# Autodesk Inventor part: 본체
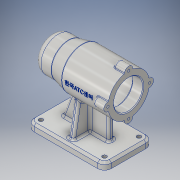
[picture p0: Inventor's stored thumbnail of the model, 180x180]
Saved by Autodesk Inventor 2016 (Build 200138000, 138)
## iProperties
Created: 2019-07
Part Number: 본체
Material: 알루미늄 6061
Document SubType Name: Modeling
Designer: 3sil_0101
Density: 2.7 g/cm^3
Appearance: 알루미늄 - 평지
Mass: 644.388 g
Surface Area: 654.094 cm^2
Volume: 238.662 cm^3
Author: 3sil_0101
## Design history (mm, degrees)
sketch "스케치1"
  geometry: L1 (56, 35)-(-56, 35); L2 (-56, 35)-(-56, -35); L3 (-56, -35)-(56, -35); L4 (56, -35)-(56, 35); L5 (56, 35)-(-56, -35); L6 (-56, 35)-(56, -35); 1 further point
  constraints: 12 end point, 2 midpoint, 2 parallel, 1 horizontal, 1 perpendicular
  dimensions: "d0" = 70 distance between parallel lines of L1 L3; "d1" = 112 distance between parallel lines of L4 L2
extrude "돌출1" new body sketch "스케치1" distance "d2" = 10; taper "d3" = 0 deg
fillet "모깎기1" dims "d4" = 10
sketch "스케치2"
  geometry: L1 (56, 10)-(56, 0) reference; L2 (-56, 0)-(-56, 10) reference; L3 (56, 80)-(-11, 80); L4 (-11, 80)-(-11, 110); L5 (-11, 110)-(56, 110); L6 (56, 110)-(56, 80); L7 (-11, 110)-(-31, 105); L8 (-31, 105)-(-31, 80); L9 (-31, 80)-(-11, 80); L10 (-31, 80)-(-56, 80); L11 (-56, 80)-(-56, 105); L12 (-56, 105)-(-31, 105); L13 (-31, 105)-(-31, 80); L14 (46, 0)-(-46, 0) reference; 1 further point
  constraints: 22 end point, 4 parallel, 2 collinear, 2 horizontal, 2 perpendicular, 1 vertical
  dimensions: "d7" = 112 distance between parallel lines of L6 L11; "d8" = 25 distance between parallel lines of L8 L11; "d9" = 45 distance between parallel lines of L11 L4; "d10" = 60 diameter of L5 L3; "d11" = 50 diameter of L12 L10; "d13" = 80 distance between parallel lines of L14 L3
revolve "회전1" sketch "스케치2" stored, may be unused: angle "d14" = 90 deg
sketch "스케치5"
  geometry: L1 (-4, -4)-(31, -4); L2 (31, -4)-(31, 4); L3 (31, 4)-(-4, 4); L4 (-4, 4)-(-4, -4); L5 (56, -25)-(56, 25) reference; L6 (-46, -35)-(46, -35) reference; L7 (-56, 25)-(-56, -25) reference; L8 (46, 35)-(-46, 35) reference; L9 (-46, -35)-(46, -35) reference; L10 (56, 0)-(-56, 0); L11 (0, 35)-(0, -35); A1 r 10 centre (46, -25) between (46, -35) and (56, -25) reference; A2 r 10 centre (-46, -25) between (-56, -25) and (-46, -35) reference; A3 r 10 centre (-46, 25) between (-46, 35) and (-56, 25) reference; A4 r 10 centre (46, 25) between (56, 25) and (46, 35) reference; 1 further point
  constraints: 12 end point, 4 midpoint, 2 parallel, 1 horizontal, 1 perpendicular, 1 other
  dimensions: "d28" = 25 distance between parallel lines of L5 L2; "d29" = 8 distance between parallel lines of L1 L3; "d54" = 4 distance between parallel lines of L11 L4
extrude "돌출3" join sketch "스케치5" stored distance "d30" = 10; taper "d31" = 0 deg
sketch "스케치6"
  geometry: L1 (56, 50)-(56, 110) reference; L2 (31, 50.268)-(-4, 50.268) reference; L3 (-11, 50)-(-11, 110) reference; L4 (-4, 50.268)-(31, 50.268) reference; L5 (31, 50.268)-(31, 50.268) reference; L6 (-56, 55)-(-56, 105) reference; L7 (-31, 55)-(-31, 105) reference; L8 (-11, 50)-(-11, 110) reference; L9 (-31, 55)-(-31, 105) reference; L10 (56, 50)-(56, 110) reference; L11 (56, 80)-(41, 80); L12 (41, 80)-(41, 101); L13 (41, 101)-(56, 101); L14 (56, 101)-(56, 80); L15 (41, 80)-(-13, 80); L16 (-13, 80)-(-13, 104); L17 (-13, 104)-(41, 104); L18 (41, 104)-(41, 80); L19 (-13, 80)-(-25, 80); L20 (-25, 80)-(-25, 101); L21 (-25, 101)-(-13, 101); L22 (-13, 101)-(-13, 80); L23 (-25, 80)-(-43, 80); L24 (-43, 80)-(-43, 97.5); L25 (-43, 97.5)-(-25, 97.5); L26 (-25, 97.5)-(-25, 80); L27 (-43, 80)-(-47, 80); L28 (-47, 80)-(-47, 96); L29 (-47, 96)-(-43, 96); L30 (-43, 96)-(-43, 80); L31 (-47, 80)-(-50, 80); L32 (-50, 80)-(-50, 90.5); L33 (-50, 90.5)-(-47, 90.5); L34 (-47, 90.5)-(-47, 80); L35 (-4, 50.268)-(-4, 50.268) reference; 1 further point
  constraints: 48 end point, 12 parallel, 6 horizontal, 6 perpendicular, 1 midpoint
  dimensions: "d32" = 42 diameter of L13 L11; "d33" = 48 diameter of L17 L15; "d34" = 15 distance between parallel lines of L1 L12; "d35" = 54 distance between parallel lines of L12 L16; "d36" = 42 diameter of L21 L19; "d37" = 12 distance between parallel lines of L16 L26; "d38" = 18 distance between parallel lines of L24 L26; "d39" = 4 distance between parallel lines of L24 L28; "d40" = 3 distance between parallel lines of L34 L32; "d41" = 35 diameter of L25 L23; "d42" = 32 diameter of L29 L27; "d43" = 21 diameter of L33 L31
revolve "회전2" sketch "스케치6" stored, may be unused: angle "d44" = 90 deg
sketch "스케치7"
  geometry: C1 r 21 at (0, 0) reference; C2 r 6 at (0, 30); 3 further points
  constraints: 3 vertical alignment, 1 centre point, 2 other
  dimensions: "d45" = 6 radius of C2
extrude "돌출4" join sketch "스케치7" distance "d46" = 16; taper "d47" = 0 deg
sketch "스케치8"
  geometry: L1 (10, 25)-(10, -25) reference; L2 (10, 35)-(10, 25) reference; L3 (10, 35)-(0, 35) reference; L4 (57.334, 19.654)-(10, 28); C1 r 21 at (80, 0) reference; A1 r 30 centre (80, 0) between (74.03, 29.4) and (50.6, 5.97) reference; A2 r 6 centre (50, 0) between (50.6, 5.97) and (50.6, -5.97) reference; A3 r 30 centre (80, 0) between (50.6, -5.97) and (74.03, -29.4) reference; A4 r 6 centre (80, -30) between (74.03, -29.4) and (85.97, -29.4) reference; A5 r 30 centre (80, 0) between (85.97, -29.4) and (109.4, -5.97) reference; A6 r 6 centre (110, 0) between (109.4, -5.97) and (109.4, 5.97) reference; A7 r 30 centre (80, 0) between (109.4, 5.97) and (85.97, 29.4) reference; A8 r 6 centre (80, 30) between (85.97, 29.4) and (74.03, 29.4) reference; A9 r 30 centre (80, 0) between (74.03, 29.4) and (50.6, 5.97) reference; 1 further point
  constraints: 2 end point, 2 point on circle, 1 point on line
  dimensions: "d52" = 7 distance from line of L3 L4.end; "d53" = 100 deg angle of L2 L4
feature "리브2" sketch "스케치8" dims "d55" = 1, "d56" = 8, "d57" = 0, "d58" = 0, "d59" = 1, "d60" = 1
sketch "스케치9"
  geometry: L1 (-31, 55)-(-11, 50) reference; L2 (46, 10)-(-46, 10) reference; L3 (-56, 10)-(-46, 10) reference; L4 (-56, 0)-(-56, 10) reference; L5 (-20.57, 52.393)-(-36, 10); 1 further point
  constraints: 2 end point, 2 point on line
  dimensions: "d61" = 110 deg angle of L2 L5; "d62" = 20 distance from line of L4 L5.end
feature "리브3" sketch "스케치9" dims "d63" = 1, "d64" = 8, "d65" = 0, "d66" = 0, "d67" = 1, "d68" = 1
chamfer "모따기1" distance "d69" = 3; stored, may be unused: second distance "d70" = 2, angle "d71" = 45 deg
fillet "모깎기4" dims "d74" = 3
fillet "모깎기5" dims "d75" = 10
fillet "모깎기6" dims "d76" = 3
chamfer "모따기2" distance "d77" = 1; stored, may be unused: second distance "d78" = 2, angle "d79" = 45 deg
fillet "모깎기7" dims "d80" = 3
sketch "스케치10"
  geometry: L1 (56, -25)-(56, 25) reference; L2 (-46, -35)-(46, -35) reference; L3 (-56, 25)-(-56, -25) reference; L4 (46, 35)-(-46, 35) reference; A1 r 10 centre (46, -25) between (46, -35) and (56, -25) reference; A2 r 10 centre (-46, -25) between (-56, -25) and (-46, -35) reference; A3 r 10 centre (-46, 25) between (-46, 35) and (-56, 25) reference; A4 r 10 centre (46, 25) between (56, 25) and (46, 35) reference; 5 further points
  constraints: 4 coincident
hole "구멍1" sketch "스케치10" at (-46, 25), (46, 25), (46, -25), (-46, -25) diameter "d82" = 6; stored, may be unused: countersink angle "d86" = 90 deg, drill point angle "d88" = 118 deg; dims "d83" = 6, "d84" = 4, "d85" = 2, "d87" = 8
fillet "모깎기9" dims "d97" = 3
fillet "모깎기10" dims "d98" = 0.3
fillet "모깎기11" dims "d99" = 3
node "작업 평면1"
sketch "스케치12"
  geometry: L1 (56, 85.97)-(56, 109.4) reference; L2 (56, 86)-(56, 74) reference; 4 further points
  constraints: 1 horizontal alignment, 1 midpoint, 1 other
  dimensions: "d101" = 42 distance from line of L1 point (14, 80)
feature "엠보싱1" sketch "스케치12" dims "d0" = 70, "d1" = 112, "d7" = 112, "d8" = 25, "d9" = 45, "d10" = 60, "d11" = 50, "d13" = 80, "d102" = 0.5, "d103" = 0
fillet "모깎기12" dims "d104" = 1
sketch "스케치13"
  geometry: C1 r 22 at (30, 0) reference; A1 r 1 centre (23.003, 30.2) between (23.229, 29.226) and (24.002, 30.171) reference; A2 r 30 centre (30, 0) between (23.229, 29.226) and (0.774, 6.771) reference; A3 r 1 centre (-0.2, 6.997) between (-0.171, 5.998) and (0.774, 6.771) reference; A4 r 6 centre (0, 0) between (-0.171, 5.998) and (-0.171, -5.998) reference; A5 r 1 centre (-0.2, -6.997) between (0.774, -6.771) and (-0.171, -5.998) reference; A6 r 30 centre (30, 0) between (0.774, -6.771) and (23.229, -29.226) reference; A7 r 1 centre (23.003, -30.2) between (24.002, -30.171) and (23.229, -29.226) reference; A8 r 6 centre (30, -30) between (24.002, -30.171) and (35.998, -30.171) reference; A9 r 1 centre (36.997, -30.2) between (36.771, -29.226) and (35.998, -30.171) reference; A10 r 30 centre (30, 0) between (36.771, -29.226) and (59.226, -6.771) reference; A11 r 1 centre (60.2, -6.997) between (60.171, -5.998) and (59.226, -6.771) reference; A12 r 6 centre (60, 0) between (60.171, -5.998) and (60.171, 5.998) reference; A13 r 1 centre (60.2, 6.997) between (59.226, 6.771) and (60.171, 5.998) reference; A14 r 30 centre (30, 0) between (59.226, 6.771) and (36.771, 29.226) reference; A15 r 1 centre (36.997, 30.2) between (35.998, 30.171) and (36.771, 29.226) reference; A16 r 6 centre (30, 30) between (35.998, 30.171) and (24.002, 30.171) reference; 2 further points
  constraints: 1 coincident
hole "구멍3" sketch "스케치13" at (30, 30) diameter "d105" = 3.242; stored, may be unused: countersink angle "d109" = 90 deg, drill point angle "d111" = 118 deg; dims "d106" = 8, "d107" = 4, "d108" = 2, "d110" = 11
fillet "모깎기14" dims "d119" = 3
fillet "모깎기15" dims "d120" = 3
node "솔리드1"
pattern_circular "원형 패턴1" dims angle "d49" = 360 deg
mirror "대칭1"
pattern_circular "원형 패턴2" dims angle "d113" = 360 deg
node "투영된 루프2"
node "투영된 루프3"
node "투영된 루프4"
node "투영된 루프5"
node "투영된 루프6"
node "투영된 루프7"
node "투영된 루프8"
node "투영된 루프10"
